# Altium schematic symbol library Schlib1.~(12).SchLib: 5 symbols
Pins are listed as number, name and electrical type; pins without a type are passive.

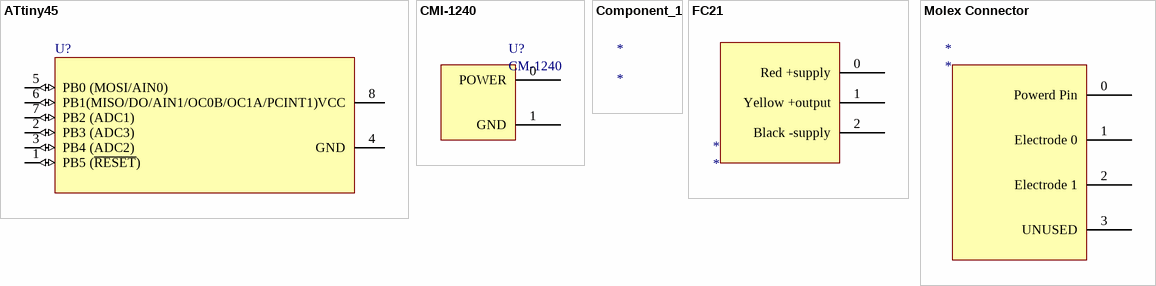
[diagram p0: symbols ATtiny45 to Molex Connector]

## ATtiny45
designator U?
8-Bit AVR Microcontroller with 1K Byte of Flash Memory
3D model 8S2 (8-Pin Small Outline Package 1.27 mm Pitch)
footprint SOIC8
footprint 8S2_N (SOP, 8-Leads, Body 5.3x5.3mm, Pitch 1.27mm, IPC Medium Density)
footprint 8S2_M (SOP, 8-Leads, Body 5.3x5.3mm, Pitch 1.27mm, IPC Low Density)
pins: 1 PB5 (~{RESET}) (io), 2 PB3 (ADC3) (io), 3 PB4 (ADC2) (io), 4 GND (power), 5 PB0 (MOSI/AIN0) (io), 6 PB1(MISO/DO/AIN1/OC0B/OC1A/PCINT1) (io), 7 PB2 (ADC1) (io), 8 VCC (power)

## CMI-1240
designator U?, comment CM-1240
footprint CMI-1240-buzzer
pins: 0 POWER "Power", 1 GND

## Component_1
designator *

## FC21
designator *
footprint FC21-Load Cell
pins: 0 Red +supply, 1 Yellow +output, 2 Black -supply

## Molex Connector
designator *
footprint 4 PIN Molex
pins: 0 Powerd Pin, 1 Electrode 0, 2 Electrode 1, 3 UNUSED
